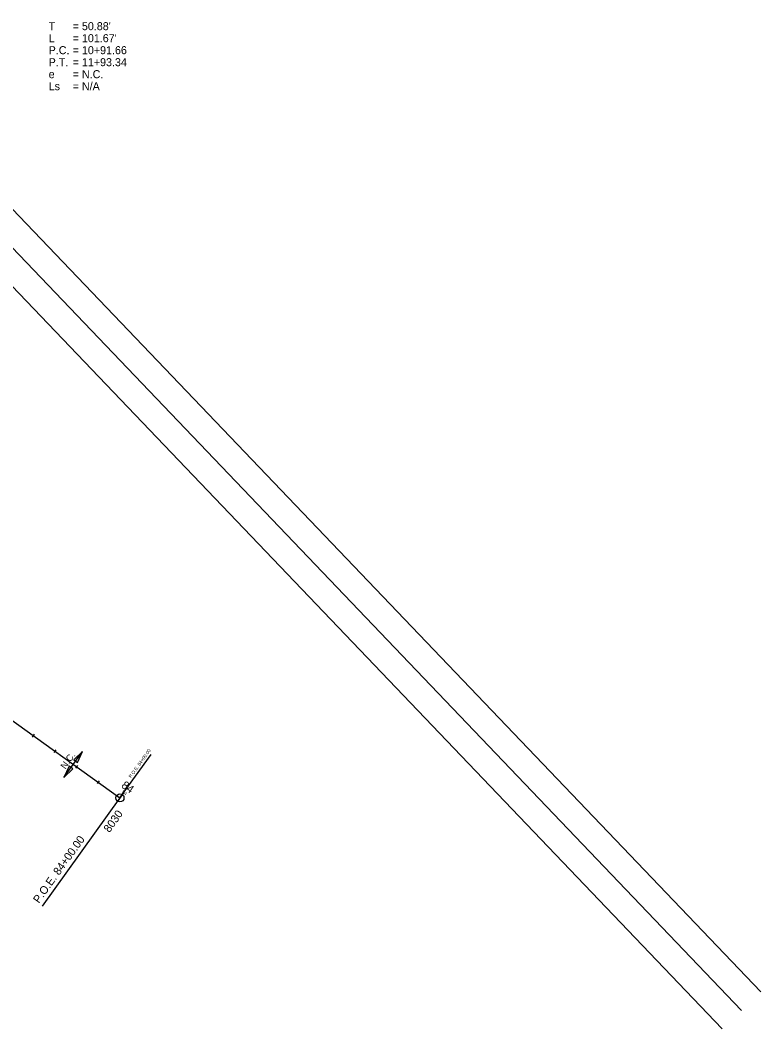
# Model space of a CAD drawing. Extents: x 1708585 to 1714116, y 541444 to 545437.
# Drawn here: x 1712816 to 1713371, y 542879 to 543635 of the extents above; entities that cross this region are included whole.
import ezdxf

# ---------------------------------------------------------------- set-up
doc = ezdxf.new("R2010")
doc.units = 0
for name, color, linetype in [('CL_Highway_2', 7, 'Continuous'), ('CL_Highway_2_40_PText', 7, 'Continuous'), ('CL_Highway_2_40_Sta', 7, 'Continuous'), ('CL_Highway_2_PText', 7, 'Continuous'), ('CL_Highway_2_Sta', 7, 'Continuous'), ('CL_Railroad', 7, 'Continuous'), ('CurveData_100', 7, 'Continuous'), ('Point_CL_Highway_2', 7, 'Continuous'), ('Point_Number', 7, 'Continuous'), ('R_SE_Slope', 7, 'Continuous')]:
    doc.layers.add(name, color=color, linetype=linetype)

msp = doc.modelspace()

# ---------------------------------------------------------------- linework, layer by layer
at = {"layer": 'CL_Highway_2'}
msp.add_line((1712734.05, 543164.87), (1712890.94, 543052.31), dxfattribs=at)
at = {"layer": 'CL_Highway_2_40_PText'}
msp.add_lwpolyline([(1712890.94, 543052.31), (1712914.26, 543084.81)], dxfattribs=at)
at = {"layer": 'CL_Highway_2_40_Sta'}
for points in [[(1712826.67, 543099.96), (1712825.21, 543097.93)], [(1712842.92, 543088.3), (1712841.46, 543086.27)], [(1712859.17, 543076.65), (1712857.71, 543074.61)], [(1712875.42, 543064.99), (1712873.96, 543062.96)], [(1712892.4, 543054.34), (1712889.49, 543050.28)]]:
    msp.add_lwpolyline(points, dxfattribs=at)
at = {"layer": 'CL_Highway_2_PText'}
msp.add_lwpolyline([(1712890.94, 543052.31), (1712832.65, 542971.06)], dxfattribs=at)
at = {"layer": 'CL_Highway_2_Sta'}
msp.add_lwpolyline([(1712893.86, 543056.38), (1712890.94, 543052.31)], dxfattribs=at)
at = {"layer": 'CL_Railroad'}
for p, q in [((1710952.7, 545436.87), (1713371.13, 542906.81)), ((1710938.24, 545423.05), (1713356.67, 542892.99)), ((1710923.78, 545409.23), (1713342.21, 542879.17))]:
    msp.add_line(p, q, dxfattribs=at)
at = {"layer": 'Point_CL_Highway_2'}
msp.add_circle((1712890.94, 543052.31), 3, dxfattribs=at)
at = {"layer": 'R_SE_Slope'}
msp.add_line((1712848.94, 543067.68), (1712862.93, 543087.18), dxfattribs=at)
for points in [[(1712856.31, 543080.85), (1712859.05, 543078.89), (1712862.93, 543087.18)], [(1712855.55, 543074.01), (1712852.81, 543075.98), (1712848.94, 543067.68)]]:
    msp.add_lwpolyline(points, close=True, dxfattribs=at)

# ---------------------------------------------------------------- texts
at = {"layer": 'CL_Highway_2'}
msp.add_text('84', height=6, rotation=324.3428, dxfattribs=at).set_placement((1712891.45, 543060.56))
at = {"layer": 'CL_Highway_2_40_PText'}
msp.add_text('P.O.E. 84+00.00', height=2.5, rotation=54.3428, dxfattribs=at).set_placement((1712899.3, 543066.96))
at = {"layer": 'CL_Highway_2_40_Sta'}
msp.add_text('84', height=2.5, rotation=324.3428, dxfattribs=at).set_placement((1712891.94, 543056.21))
at = {"layer": 'CL_Highway_2_PText'}
msp.add_text('P.O.E. 84+00.00', height=6, rotation=54.3428, dxfattribs=at).set_placement((1712830.21, 542972.81))
at = {"layer": 'CL_Highway_2_Sta'}
msp.add_text('84', height=6, rotation=324.3428, dxfattribs=at).set_placement((1712891.45, 543060.56))
at = {"layer": 'CurveData_100'}
for s, p in [('T', (1712837.5, 543627.81)), ("= 50.88'", (1712855.5, 543627.81)), ('L', (1712837.5, 543618.81)), ("= 101.67'", (1712855.5, 543618.81)), ('P.C.', (1712837.5, 543609.81)), ('= 10+91.66', (1712855.5, 543609.81)), ('P.T.', (1712837.5, 543600.81)), ('= 11+93.34', (1712855.5, 543600.81)), ('= N.C.', (1712855.5, 543591.81)), ('e', (1712837.5, 543591.81)), ('Ls', (1712837.5, 543582.81)), ('= N/A', (1712855.5, 543582.81))]:
    msp.add_text(s, height=6, dxfattribs=at).set_placement(p)
at = {"layer": 'Point_Number'}
msp.add_text('8030', height=6, rotation=54.3428, dxfattribs=at).set_placement((1712883.05, 543025.87))
at = {"layer": 'R_SE_Slope'}
msp.add_text('N.C.', height=5, rotation=54.3428, dxfattribs=at).set_placement((1712849.99, 543073.44))

doc.saveas('drawing.dxf')
